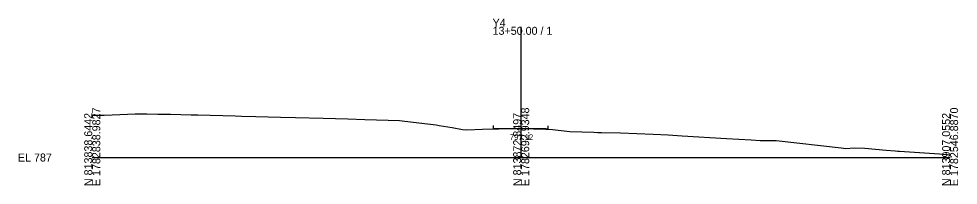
# Model space of a CAD drawing. Extents: x -26 to 3903, y -10 to 9562.
# Drawn here: x -25.7 to 302.8, y 5490.3 to 5548.5 of the extents above; entities that cross this region are included whole.
import ezdxf

# ---------------------------------------------------------------- set-up
doc = ezdxf.new("R2010")
doc.units = 0
for name, color, linetype in [('Exist Cross Section Cell', 7, 'Continuous'), ('Exist XS Center Line Elevation Label', 7, 'Continuous'), ('Exist XS Ground Line', 7, 'Continuous'), ('Prop XS EOT Tick Mark', 7, 'Continuous'), ('Prop XS Finish Grade Pavement', 7, 'Continuous')]:
    doc.layers.add(name, color=color, linetype=linetype)

msp = doc.modelspace()

# ---------------------------------------------------------------- linework, layer by layer
at = {"layer": 'Exist Cross Section Cell'}
for p, q in [((150, 5500), (150, 5545.73)), ((0, 5500), (150, 5500)), ((150, 5500), (300, 5500))]:
    msp.add_line(p, q, dxfattribs=at)
at = {"layer": 'Exist XS Ground Line'}
for p, q in [((0, 5514.79), (1.1, 5514.78)), ((1.1, 5514.78), (4.17, 5514.76)), ((4.17, 5514.76), (6.92, 5514.9)), ((6.92, 5514.9), (15.06, 5515.23)), ((15.06, 5515.23), (19.04, 5515.24)), ((19.04, 5515.24), (22.96, 5515.19)), ((22.96, 5515.19), (27.33, 5515.13)), ((27.33, 5515.13), (34.61, 5514.98)), ((34.61, 5514.98), (35.61, 5514.95)), ((35.61, 5514.95), (36.97, 5514.91)), ((36.97, 5514.91), (50.03, 5514.53)), ((50.03, 5514.53), (52.23, 5514.48)), ((52.23, 5514.48), (57.15, 5514.34)), ((57.15, 5514.34), (65.86, 5514.09)), ((65.86, 5514.09), (71.04, 5514)), ((71.04, 5514), (80.74, 5513.72)), ((80.74, 5513.72), (89.39, 5513.49)), ((89.39, 5513.49), (95.28, 5513.33)), ((95.28, 5513.33), (103.53, 5513.06)), ((103.53, 5513.06), (107.45, 5512.91)), ((107.45, 5512.91), (108.39, 5512.82)), ((108.39, 5512.82), (114.22, 5512.1)), ((114.22, 5512.1), (120.25, 5511.4)), ((120.25, 5511.4), (121.33, 5511.24)), ((121.33, 5511.24), (122.78, 5511.02)), ((122.78, 5511.02), (125.84, 5510.5)), ((125.84, 5510.5), (129.51, 5509.85)), ((129.51, 5509.85), (130.99, 5509.73)), ((130.99, 5509.73), (136.51, 5509.91)), ((136.51, 5509.91), (140.34, 5510.06)), ((140.34, 5510.06), (142.24, 5510.07)), ((142.24, 5510.07), (149.94, 5510.12)), ((149.94, 5510.12), (158.68, 5509.97)), ((158.68, 5509.97), (159.46, 5509.96)), ((159.46, 5509.96), (160.96, 5509.78)), ((160.96, 5509.78), (167.04, 5509.11)), ((167.04, 5509.11), (175.41, 5508.88)), ((175.41, 5508.88), (176.78, 5508.79)), ((176.78, 5508.79), (178.04, 5508.71)), ((178.04, 5508.71), (184.76, 5508.61)), ((184.76, 5508.61), (190.45, 5508.39)), ((190.45, 5508.39), (196.16, 5508.16)), ((196.16, 5508.16), (201.37, 5507.95)), ((201.37, 5507.95), (206.27, 5507.62)), ((206.27, 5507.62), (221.76, 5506.62)), ((221.76, 5506.62), (230.42, 5506.15)), ((230.42, 5506.15), (233.6, 5505.98)), ((233.6, 5505.98), (239.22, 5505.94)), ((239.22, 5505.94), (261.86, 5503.35)), ((261.86, 5503.35), (263.49, 5503.21)), ((263.49, 5503.21), (266.49, 5503.34)), ((266.49, 5503.34), (270.21, 5503.23)), ((270.21, 5503.23), (277.68, 5502.57)), ((277.68, 5502.57), (280.74, 5502.31)), ((280.74, 5502.31), (281.7, 5502.2)), ((281.7, 5502.2), (282.36, 5502.17)), ((282.36, 5502.17), (296.24, 5501.23)), ((296.24, 5501.23), (300, 5500.91))]:
    msp.add_line(p, q, dxfattribs=at)
at = {"layer": 'Prop XS EOT Tick Mark'}
for p, q in [((140.32, 5510.19), (140.32, 5511.19)), ((159.48, 5510.08), (159.48, 5511.08))]:
    msp.add_line(p, q, dxfattribs=at)
at = {"layer": 'Prop XS Finish Grade Pavement'}
for p, q in [((140.32, 5510.19), (140.33, 5510.19)), ((140.33, 5510.19), (142.24, 5510.2)), ((142.24, 5510.2), (149.94, 5510.24)), ((149.94, 5510.24), (158.68, 5510.1)), ((158.68, 5510.1), (159.47, 5510.09)), ((159.47, 5510.09), (159.48, 5510.08))]:
    msp.add_line(p, q, dxfattribs=at)

# ---------------------------------------------------------------- texts
at = {"layer": 'Exist Cross Section Cell'}
for s, p in [('Y4', (140, 5545.73)), ('13+50.00 / 1', (140, 5542.93)), ('EL 787', (-26, 5498.6))]:
    msp.add_text(s, height=2.8, dxfattribs=at).set_placement(p)
for s, p in [('E 1782838.9827', (2.8, 5490)), ('E 1782692.9348', (152.8, 5490)), ('E 1782546.8870', (302.8, 5490)), ('N 813838.6442', (0, 5490)), ('N 813872.8497', (150, 5490)), ('N 813907.0552', (300, 5490))]:
    msp.add_text(s, height=2.8, rotation=90, dxfattribs=at).set_placement(p)
at = {"layer": 'Exist XS Center Line Elevation Label'}
msp.add_text('797.12', height=2, dxfattribs=at).set_placement((146.03, 5506.12))

doc.saveas('drawing.dxf')
